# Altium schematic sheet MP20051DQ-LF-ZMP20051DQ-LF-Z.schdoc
size 127 x 101 mm
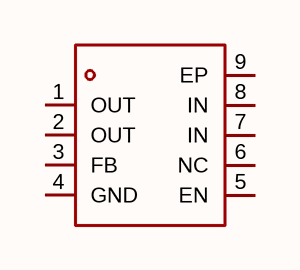
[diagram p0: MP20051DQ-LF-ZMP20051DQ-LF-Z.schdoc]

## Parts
U?  mp20051dq-lf-z  [QFN-8_L3.0-W3.0-P0.65-TL-EP2.5]  (value not drawn)

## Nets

Not connected (* = marked no-connect by the designer): U? 1(OUT) 2(OUT) 3(FB) 4(GND) 5(EN) 6(NC) 7(IN) 8(IN) 9(EP)

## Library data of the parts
U? = mp20051dq-lf-z: 输出极性:正极;工作电压:5.5V;输出电压:800mV~5V;输出电流:1A;电源纹波抑制比(PSRR):63dB@(1kHz);输出类型:可调;; Manufacturer: MPS(芯源); AddInBom: yes; ModelId: 7d7b0c6373f54773b7915f82dc80757a; ModelTransform: 118.18874,118.11,0,0,0,0,0,0,0; Output Configuration: 正极; Voltage - Supply: 5.5V; Output Current: 1A; Voltage Dropout: 140mV@(1A); standby current: 110uA; Noise: 13uVrms; Output Type: 可调; Number of Outputs: 1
